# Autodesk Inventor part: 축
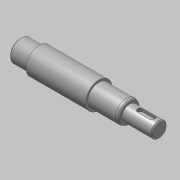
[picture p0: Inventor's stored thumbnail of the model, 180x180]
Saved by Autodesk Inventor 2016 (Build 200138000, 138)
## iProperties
Created: 2016-06
Part Number: 축
Material: 강철, 연강
Document SubType Name: Modeling
Designer: mduedu
Density: 7.86 g/cm^3
Appearance: 강철
Author: mduedu
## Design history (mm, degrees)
sketch "스케치1"
  geometry: L1 (-63, 0)-(63, 0); L2 (-63, 0)-(-63, 10); L3 (-63, 10)-(-46, 10); L4 (-46, 10)-(-46, 12); L5 (-46, 12)-(8, 12); L6 (8, 12)-(8, 10); L7 (8, 10)-(36, 10); L8 (36, 10)-(36, 7); L9 (36, 7)-(63, 7); L10 (63, 7)-(63, 0); 2 further points
  constraints: 20 end point, 5 parallel, 2 perpendicular, 1 coincident, 1 collinear, 1 horizontal, 1 midpoint, 1 vertical
  dimensions: "d0" = 126 distance of L1.start L1.end; "d2" = 14 diameter of L9 L1; "d3" = 20 diameter of L7 L1; "d4" = 24 diameter of L5 L1; "d5" = 20 diameter of L3 L1; "d6" = 17 distance of L2.end L3.end; "d7" = 27 distance of L8.end L9.end; "d8" = 55 distance from line of L5.end L10
revolve "회전1" sketch "스케치1" stored, may be unused: angle "d9" = 90 deg
sketch "스케치5"
  geometry: L1 (63, 10)-(63, -10) reference; L2 (63, -10)-(46, -10) reference; L3 (46, -10)-(46, -12) reference; L4 (46, -12)-(-8, -12) reference; L5 (-8, -12)-(-8, -10) reference; L6 (-8, -10)-(-36, -10) reference; L7 (-36, -10)-(-36, -7) reference; L8 (-36, -7)-(-63, -7) reference; L9 (-63, -7)-(-63, 7) reference; L10 (-63, 7)-(-36, 7) reference; L11 (-36, 7)-(-36, 10) reference; L12 (-36, 10)-(-8, 10) reference; L13 (-8, 10)-(-8, 12) reference; L14 (-8, 12)-(46, 12) reference; L15 (46, 12)-(46, 10) reference; L16 (46, 10)-(63, 10) reference; L17 (-63, 0)-(63, 0); L18 (-36, 8.85)-(-34.008, 10); L19 (-34.008, 10)-(-36, 10); L20 (-36, 10)-(-36, 8.85); 1 further point
  constraints: 8 end point, 2 midpoint, 2 point on line, 1 collinear, 1 perpendicular
  dimensions: "d36" = 17.7 diameter of L18.start L17; "d37" = 30 deg angle of L12 L18
revolve "회전3" sketch "스케치5" stored, may be unused: angle "d38" = 90 deg
fillet "모깎기1" dims "d13" = 4, "d39" = 0.5
node "작업 평면1"
sketch "스케치2"
  geometry: L1 (-4, 2.5)-(7, 2.5); L2 (7, -2.5)-(-4, -2.5); L3 (-4, 0)-(7, 0); L4 (-13.5, 8.561)-(-13.5, -8.561) reference; A1 r 2.5 centre (-4, 0) between (-4, 2.5) and (-4, -2.5); A2 r 2.5 centre (7, 0) between (7, -2.5) and (7, 2.5); 1 further point
  constraints: 6 end point, 4 point on circle, 3 tangent, 2 centre point, 2 parallel, 1 horizontal, 1 horizontal alignment
  dimensions: "d15" = 5 distance between parallel lines of L2 L1; "d16" = 16 dimension on A2 A1; "d40" = 7 distance edge to line of A1 L4
extrude "돌출1" cut sketch "스케치2" distance "d17" = 3; taper "d18" = 0 deg
chamfer "모따기2" distance "d19" = 1; stored, may be unused: second distance "d20" = 2, angle "d21" = 30 deg
sketch "스케치3"
  geometry: L1 (-36, -7)-(-62, -7) reference; L2 (-63, -6)-(-63, 6) reference; L3 (-39.5, -7)-(-41, -5.5); L4 (-41, -5.5)-(-41, -7); L5 (-39.5, -7)-(-41, -7); 1 further point
  constraints: 6 end point, 2 point on line, 1 collinear, 1 vertical
  dimensions: "d22" = 45 deg angle of L4 L3; "d23" = 22 distance between parallel lines of L2 L4; "d24" = 3 diameter of L3.start L4
revolve "회전2" stored, may be unused: angle "d25" = 90 deg
node "작업점1"
sketch "스케치4"
  geometry: 1 further point
hole "구멍1" sketch "스케치4" at (0, 0) diameter "d26" = 3.242; stored, may be unused: countersink angle "d30" = 90 deg, drill point angle "d32" = 120 deg; dims "d27" = 8, "d28" = 4, "d29" = 2, "d31" = 11
chamfer "모따기3" distance "d33" = 2; stored, may be unused: second distance "d34" = 2, angle "d35" = 30 deg
node "솔리드1"
node "절단 모서리 투영1"
